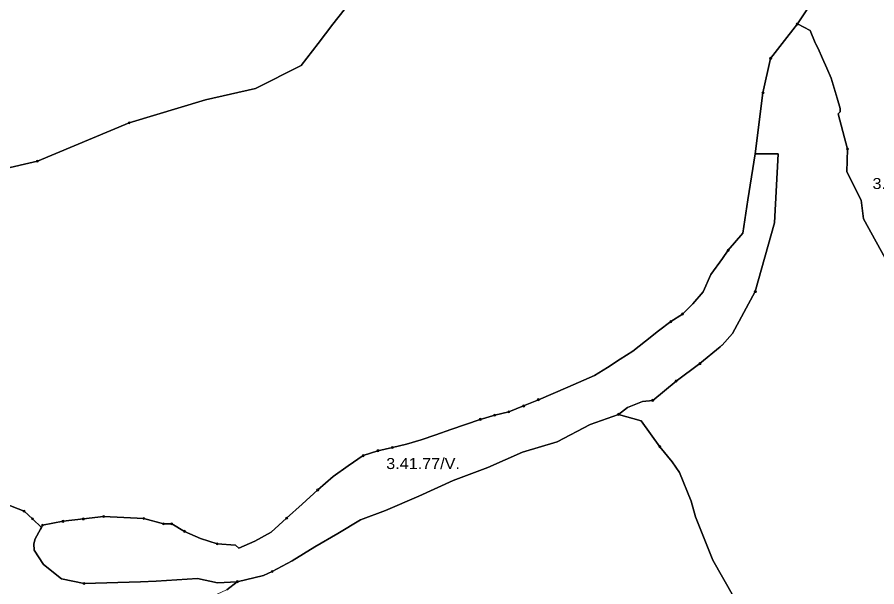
# Model space of a CAD drawing. Extents: x -650455 to -642254, y -1075222 to -1066610.
# Drawn here: x -646705 to -645923, y -1070494 to -1069976 of the extents above; entities that cross this region are included whole.
import ezdxf
from ezdxf.enums import TextEntityAlignment as Align

# ---------------------------------------------------------------- set-up
doc = ezdxf.new("R2010")
doc.units = 0
doc.header["$LTSCALE"] = 4
doc.header["$PDMODE"] = 32
doc.header["$PDSIZE"] = 2
for name, color, linetype, lineweight in [('1', 7, 'Continuous', 25), ('11', 7, 'Continuous', 13), ('12', 7, 'Continuous', 13), ('13', 7, 'Continuous', 13), ('14', 7, 'Continuous', 13), ('15', 7, 'Continuous', 13)]:
    doc.layers.add(name, color=color, linetype=linetype, lineweight=lineweight)
doc.layers.add('2', color=7, linetype='Continuous')

msp = doc.modelspace()

# ---------------------------------------------------------------- linework, layer by layer
at = {"layer": '1'}
for points in [[(-646313.5, -1069705.501), (-646346.5, -1069815.501), (-646359, -1069878.5), (-646385.5, -1069941.501), (-646417.5, -1069982.501), (-646430.839, -1070000), (-646446.211, -1070020.168), (-646487.943, -1070041.034), (-646533.153, -1070051.467), (-646602.706, -1070072.333), (-646686.17, -1070107.109), (-646776.589, -1070127.975)], [(-645892.146, -1070237.292), (-645934.808, -1070159.546), (-645937.054, -1070142.706), (-645949.965, -1070116.884), (-645949.403, -1070096.114), (-645957.823, -1070064.117), (-645955.946, -1070062.197), (-645955.946, -1070059.127), (-645958.753, -1070049.961), (-645961.472, -1070040.795), (-645964.191, -1070031.63), (-645968.226, -1070022.552), (-645972.085, -1070013.649), (-645976.12, -1070004.746), (-645978.592, -1070000), (-645978.839, -1069999.528), (-645983.4, -1069988.169), (-645994.986, -1069982.348), (-645974.12, -1069951.049), (-645958.773, -1069928.03), (-645960, -1069928)], [(-646776.589, -1070127.975), (-646686.17, -1070107.109), (-646602.706, -1070072.333), (-646533.153, -1070051.467), (-646487.943, -1070041.034), (-646446.211, -1070020.168), (-646430.839, -1070000), (-646417.5, -1069982.501), (-646385.5, -1069941.501)], [(-645974.12, -1069951.049), (-645994.986, -1069982.348), (-646008.715, -1070000), (-646019.329, -1070013.647), (-646026.284, -1070044.946), (-646033.24, -1070100.589), (-646040.195, -1070142.321), (-646044.529, -1070172.658), (-646057.984, -1070188.238), (-646063.155, -1070195.784), (-646073.776, -1070210.249), (-646080.764, -1070226.111), (-646090.127, -1070236.942), (-646099.491, -1070246.235), (-646110.112, -1070253.153), (-646121.432, -1070261.469), (-646133.032, -1070270.762), (-646144.631, -1070280.056), (-646156.231, -1070287.393), (-646167.83, -1070294.73), (-646179.43, -1070302.067), (-646203.747, -1070312.828), (-646217.164, -1070318.488), (-646230.58, -1070324.148), (-646243.996, -1070329.808), (-646257.413, -1070335.189), (-646270.27, -1070338.193), (-646283.407, -1070342.037), (-646296.823, -1070346.718), (-646310.24, -1070351.4)], [(-646071.795, -1070469.988), (-646087.776, -1070430.716), (-646091.516, -1070416.436), (-646102.056, -1070390.425), (-646108.856, -1070380.565), (-646120.077, -1070366.964), (-646137.077, -1070343.504), (-646157.707, -1070337.514), (-646149.487, -1070331.235), (-646135.809, -1070325.671), (-646126.536, -1070324.744), (-646105.207, -1070307.24), (-646083.647, -1070291.36), (-646065.1, -1070275.943), (-646064.049, -1070274.932), (-646063.394, -1070274.488), (-646054.106, -1070264.038), (-646033.24, -1070225.784), (-646015.851, -1070163.186), (-646012.374, -1070100.589), (-646033.24, -1070100.589), (-646026.284, -1070044.946), (-646019.329, -1070013.647), (-646008.715, -1070000), (-645994.986, -1069982.348), (-645983.4, -1069988.169), (-645978.839, -1069999.528), (-645978.592, -1070000), (-645976.12, -1070004.746), (-645972.085, -1070013.649), (-645968.226, -1070022.552), (-645964.191, -1070031.63), (-645961.472, -1070040.795), (-645958.753, -1070049.961), (-645955.946, -1070059.127), (-645955.946, -1070062.197), (-645957.823, -1070064.117), (-645949.403, -1070096.114), (-645949.965, -1070116.884), (-645937.054, -1070142.706)], [(-646503.1, -1070459.15), (-646488.566, -1070452.792), (-646473.612, -1070444.756), (-646459.497, -1070431.968), (-646445.382, -1070419.181), (-646431.267, -1070406.254), (-646417.291, -1070394.165), (-646403.456, -1070384.172), (-646389.899, -1070375.019), (-646376.483, -1070370.616), (-646363.346, -1070367.612), (-646350.349, -1070364.607), (-646337.072, -1070360.764), (-646323.656, -1070356.082), (-646310.24, -1070351.4), (-646296.823, -1070346.718), (-646283.407, -1070342.037), (-646270.27, -1070338.193), (-646257.413, -1070335.189), (-646243.996, -1070329.808), (-646230.58, -1070324.148), (-646217.164, -1070318.488), (-646203.747, -1070312.828), (-646179.43, -1070302.067), (-646167.83, -1070294.73), (-646156.231, -1070287.393), (-646144.631, -1070280.056), (-646133.032, -1070270.762), (-646121.432, -1070261.469), (-646110.112, -1070253.153), (-646099.491, -1070246.235), (-646090.127, -1070236.942), (-646080.764, -1070226.111), (-646073.776, -1070210.249), (-646063.155, -1070195.784), (-646057.984, -1070188.238), (-646044.529, -1070172.658), (-646040.195, -1070142.321), (-646033.24, -1070100.589), (-646012.374, -1070100.589)], [(-646012.374, -1070100.589), (-646015.851, -1070163.186), (-646033.24, -1070225.784), (-646054.106, -1070264.038), (-646063.394, -1070274.488), (-646064.049, -1070274.932), (-646065.1, -1070275.943), (-646083.647, -1070291.36), (-646105.207, -1070307.24), (-646126.536, -1070324.744), (-646135.809, -1070325.671), (-646149.487, -1070331.235), (-646157.707, -1070337.514)], [(-645937.054, -1070142.706), (-645934.808, -1070159.546), (-645892.146, -1070237.292), (-645883.165, -1070254.133), (-645864.64, -1070297.356), (-645851.729, -1070325.985), (-645836.012, -1070342.825), (-645812.997, -1070356.859), (-645785.491, -1070380.435), (-645768.65, -1070402.889), (-645763.626, -1070420.193)], [(-646157.707, -1070337.514), (-646183.567, -1070346.768), (-646213.473, -1070362.417), (-646245.003, -1070372.038), (-646276.532, -1070385.832), (-646308.062, -1070397.772), (-646339.359, -1070411.797), (-646369.729, -1070424.896), (-646392.217, -1070433.59), (-646413.082, -1070445.761), (-646433.947, -1070457.932), (-646454.58, -1070470.799), (-646472.663, -1070480.42), (-646480.546, -1070484.129), (-646504.412, -1070489.744), (-646522.293, -1070490.738), (-646540.7, -1070486.685), (-646578.106, -1070489.302), (-646592.291, -1070489.809), (-646643.714, -1070491.413), (-646664.401, -1070487.107), (-646680.613, -1070473.935), (-646689.056, -1070460.931), (-646689.394, -1070455.19), (-646688.291, -1070450.623), (-646683.243, -1070441.891), (-646682.529, -1070440.373), (-646681.566, -1070438.327), (-646662.839, -1070434.764), (-646644.391, -1070432.597), (-646625.944, -1070430.431), (-646607.636, -1070431.34), (-646589.328, -1070432.248), (-646571.44, -1070437.069), (-646564.033, -1070437.069), (-646552.433, -1070443.987), (-646537.759, -1070450.346), (-646522.666, -1070455.307), (-646505.895, -1070456.635), (-646503.1, -1070459.15)], [(-646513.93, -1070496.996), (-646504.412, -1070489.744), (-646480.546, -1070484.129), (-646472.663, -1070480.42), (-646454.58, -1070470.799), (-646433.947, -1070457.932), (-646413.082, -1070445.761), (-646392.217, -1070433.59), (-646369.729, -1070424.896), (-646339.359, -1070411.797), (-646308.062, -1070397.772), (-646276.532, -1070385.832), (-646245.003, -1070372.038), (-646213.473, -1070362.417), (-646183.567, -1070346.768), (-646157.707, -1070337.514), (-646137.077, -1070343.504), (-646120.077, -1070366.964), (-646108.856, -1070380.565), (-646102.056, -1070390.425), (-646091.516, -1070416.436), (-646087.776, -1070430.716), (-646071.795, -1070469.988), (-646053.095, -1070503.139)], [(-646310.24, -1070351.4), (-646323.656, -1070356.082), (-646337.072, -1070360.764), (-646350.349, -1070364.607), (-646363.346, -1070367.612), (-646376.483, -1070370.616), (-646389.899, -1070375.019), (-646403.456, -1070384.172), (-646417.291, -1070394.165), (-646431.267, -1070406.254), (-646445.382, -1070419.181), (-646459.497, -1070431.968), (-646473.612, -1070444.756), (-646488.566, -1070452.792), (-646503.1, -1070459.15), (-646505.895, -1070456.635), (-646522.666, -1070455.307), (-646537.759, -1070450.346), (-646552.433, -1070443.987), (-646564.033, -1070437.069), (-646571.44, -1070437.069), (-646589.328, -1070432.248), (-646607.636, -1070431.34), (-646625.944, -1070430.431), (-646644.391, -1070432.597), (-646662.839, -1070434.764), (-646681.566, -1070438.327), (-646682.529, -1070440.373), (-646690.65, -1070432.527), (-646698.336, -1070425.54), (-646716.085, -1070418.622)], [(-646895.25, -1070424.491), (-646877.361, -1070423.583), (-646859.613, -1070422.675), (-646841.444, -1070420.229), (-646823.276, -1070420.998), (-646805.248, -1070421.766), (-646787.22, -1070420.299), (-646769.192, -1070417.294), (-646751.583, -1070414.289), (-646733.694, -1070416.456), (-646716.085, -1070418.622), (-646698.336, -1070425.54), (-646690.65, -1070432.527), (-646682.529, -1070440.373)], [(-646682.529, -1070440.373), (-646683.243, -1070441.891), (-646688.291, -1070450.623), (-646689.394, -1070455.19), (-646689.056, -1070460.931), (-646680.613, -1070473.935), (-646664.401, -1070487.107), (-646643.714, -1070491.413), (-646592.291, -1070489.809), (-646578.106, -1070489.302), (-646540.7, -1070486.685), (-646522.293, -1070490.738), (-646504.412, -1070489.744), (-646513.93, -1070496.996)], [(-645920.242, -1070713.679), (-645927.962, -1070711.588), (-645950.317, -1070694.38), (-645965.032, -1070672.106), (-645972.912, -1070658.757), (-645982.884, -1070639.297), (-645992.731, -1070624.604), (-645999.333, -1070608.761), (-646000.735, -1070603.916), (-646002.692, -1070598.86), (-646005.067, -1070591.608), (-646007.731, -1070584.143), (-646009.999, -1070577.784), (-646016.721, -1070567.029), (-646017.857, -1070565.514), (-646032.694, -1070537.65), (-646053.095, -1070503.139), (-646071.795, -1070469.988)]]:
    msp.add_lwpolyline(points, dxfattribs=at)
at = {"layer": '11'}
for p, q in [((-646243.996, -1070329.808), (-646230.58, -1070324.148)), ((-646270.27, -1070338.193), (-646257.413, -1070335.189)), ((-646257.413, -1070335.189), (-646243.996, -1070329.808)), ((-646698.336, -1070425.54), (-646690.65, -1070432.527)), ((-646662.839, -1070434.764), (-646644.391, -1070432.597)), ((-646644.391, -1070432.597), (-646625.944, -1070430.431)), ((-646589.328, -1070432.248), (-646571.44, -1070437.069)), ((-646571.44, -1070437.069), (-646564.033, -1070437.069)), ((-646564.033, -1070437.069), (-646552.433, -1070443.987))]:
    msp.add_line(p, q, dxfattribs=at)
for points in [[(-645994.986, -1069982.348), (-645974.12, -1069951.049), (-645958.773, -1069928.03), (-645960, -1069928), (-645957.5, -1069916.501), (-645945.5, -1069826), (-645941.5, -1069786)], [(-646359, -1069878.5), (-646385.5, -1069941.501), (-646417.5, -1069982.501), (-646430.839, -1070000), (-646446.211, -1070020.168), (-646487.943, -1070041.034), (-646533.153, -1070051.467), (-646602.706, -1070072.333), (-646686.17, -1070107.109)], [(-646019.329, -1070013.647), (-646008.715, -1070000), (-645994.986, -1069982.348)], [(-646057.984, -1070188.238), (-646044.529, -1070172.658), (-646040.195, -1070142.321), (-646033.24, -1070100.589), (-646026.284, -1070044.946), (-646019.329, -1070013.647)], [(-646686.17, -1070107.109), (-646776.589, -1070127.975), (-646839.187, -1070117.542)], [(-646099.491, -1070246.235), (-646090.127, -1070236.942), (-646080.764, -1070226.111), (-646073.776, -1070210.249), (-646063.155, -1070195.784), (-646057.984, -1070188.238)], [(-646230.58, -1070324.148), (-646217.164, -1070318.488), (-646203.747, -1070312.828), (-646179.43, -1070302.067), (-646167.83, -1070294.73), (-646156.231, -1070287.393), (-646144.631, -1070280.056), (-646133.032, -1070270.762), (-646121.432, -1070261.469), (-646110.112, -1070253.153), (-646099.491, -1070246.235)], [(-646363.346, -1070367.612), (-646350.349, -1070364.607), (-646337.072, -1070360.764), (-646323.656, -1070356.082), (-646310.24, -1070351.4), (-646296.823, -1070346.718), (-646283.407, -1070342.037), (-646270.27, -1070338.193)], [(-646552.433, -1070443.987), (-646537.759, -1070450.346), (-646522.666, -1070455.307), (-646505.895, -1070456.635), (-646503.1, -1070459.15), (-646488.566, -1070452.792), (-646473.612, -1070444.756), (-646459.497, -1070431.968), (-646445.382, -1070419.181), (-646431.267, -1070406.254), (-646417.291, -1070394.165), (-646403.456, -1070384.172), (-646389.899, -1070375.019), (-646376.483, -1070370.616), (-646363.346, -1070367.612)], [(-646948.775, -1070423.304), (-646930.747, -1070423.513), (-646912.999, -1070424.002), (-646895.25, -1070424.491), (-646877.361, -1070423.583), (-646859.613, -1070422.675), (-646841.444, -1070420.229), (-646823.276, -1070420.998), (-646805.248, -1070421.766), (-646787.22, -1070420.299), (-646769.192, -1070417.294), (-646751.583, -1070414.289), (-646733.694, -1070416.456), (-646716.085, -1070418.622), (-646698.336, -1070425.54)], [(-646690.65, -1070432.527), (-646682.529, -1070440.373), (-646681.566, -1070438.327), (-646662.839, -1070434.764)], [(-646625.944, -1070430.431), (-646607.636, -1070431.34), (-646589.328, -1070432.248)]]:
    msp.add_lwpolyline(points, dxfattribs=at)
for p in [(-645994.986, -1069982.348), (-646019.329, -1070013.647), (-646686.17, -1070107.109), (-646057.984, -1070188.238), (-646099.491, -1070246.235), (-646230.58, -1070324.148), (-646257.413, -1070335.189), (-646243.996, -1070329.808), (-646270.27, -1070338.193), (-646363.346, -1070367.612), (-646698.336, -1070425.54), (-646690.65, -1070432.527), (-646662.839, -1070434.764), (-646644.391, -1070432.597), (-646625.944, -1070430.431), (-646589.328, -1070432.248), (-646571.44, -1070437.069), (-646564.033, -1070437.069), (-646552.433, -1070443.987)]:
    msp.add_point(p, dxfattribs=at)
at = {"layer": '12'}
for points in [[(-645994.986, -1069982.348), (-646008.715, -1070000), (-646019.329, -1070013.647), (-646026.284, -1070044.946)], [(-645892.146, -1070237.292), (-645934.808, -1070159.546), (-645937.054, -1070142.706), (-645949.965, -1070116.884), (-645949.403, -1070096.114), (-645957.823, -1070064.117), (-645955.946, -1070062.197), (-645955.946, -1070059.127), (-645958.753, -1070049.961), (-645961.472, -1070040.795), (-645964.191, -1070031.63), (-645968.226, -1070022.552), (-645972.085, -1070013.649), (-645976.12, -1070004.746), (-645978.592, -1070000), (-645978.839, -1069999.528), (-645983.4, -1069988.169), (-645994.986, -1069982.348)], [(-646026.284, -1070044.946), (-646033.24, -1070100.589), (-646012.374, -1070100.589), (-646015.851, -1070163.186), (-646033.24, -1070225.784)], [(-646033.24, -1070225.784), (-646054.106, -1070264.038), (-646063.394, -1070274.488), (-646064.049, -1070274.932), (-646065.1, -1070275.943), (-646083.647, -1070291.36)], [(-646083.647, -1070291.36), (-646105.207, -1070307.24), (-646126.536, -1070324.744), (-646135.809, -1070325.671), (-646149.487, -1070331.235), (-646157.707, -1070337.514), (-646137.077, -1070343.504), (-646120.077, -1070366.964), (-646108.856, -1070380.565), (-646102.056, -1070390.425), (-646091.516, -1070416.436), (-646087.776, -1070430.716), (-646071.795, -1070469.988), (-646053.095, -1070503.139), (-646032.694, -1070537.65), (-646017.857, -1070565.514), (-646016.721, -1070567.029), (-646009.999, -1070577.784), (-646007.731, -1070584.143), (-646005.067, -1070591.608), (-646002.692, -1070598.86), (-646000.735, -1070603.916)], [(-646157.707, -1070337.514), (-646183.567, -1070346.768), (-646213.473, -1070362.417), (-646245.003, -1070372.038), (-646276.532, -1070385.832), (-646308.062, -1070397.772), (-646339.359, -1070411.797), (-646369.729, -1070424.896), (-646392.217, -1070433.59), (-646413.082, -1070445.761), (-646433.947, -1070457.932), (-646454.58, -1070470.799), (-646472.663, -1070480.42), (-646480.546, -1070484.129), (-646504.412, -1070489.744)], [(-646120.077, -1070366.964), (-646137.077, -1070343.504), (-646157.707, -1070337.514)], [(-646014.913, -1070609.041), (-646008.134, -1070603.149), (-646004.664, -1070600.284), (-646002.692, -1070598.86), (-646005.067, -1070591.608), (-646007.731, -1070584.143), (-646009.999, -1070577.784), (-646016.721, -1070567.029), (-646017.857, -1070565.514), (-646032.694, -1070537.65), (-646053.095, -1070503.139), (-646071.795, -1070469.988), (-646087.776, -1070430.716), (-646091.516, -1070416.436), (-646102.056, -1070390.425), (-646108.856, -1070380.565), (-646120.077, -1070366.964)], [(-646504.412, -1070489.744), (-646513.93, -1070496.996), (-646514.69, -1070497.343), (-646529.926, -1070504.299)]]:
    msp.add_lwpolyline(points, dxfattribs=at)
for p in [(-645994.986, -1069982.348), (-646026.284, -1070044.946), (-646033.24, -1070225.784), (-646083.647, -1070291.36), (-646157.707, -1070337.514), (-646120.077, -1070366.964), (-646504.412, -1070489.744)]:
    msp.add_point(p, dxfattribs=at)
at = {"layer": '13'}
for points in [[(-646602.706, -1070072.333), (-646533.153, -1070051.467), (-646487.943, -1070041.034), (-646446.211, -1070020.168), (-646430.839, -1070000), (-646417.5, -1069982.501), (-646385.5, -1069941.501)], [(-646776.589, -1070127.975), (-646686.17, -1070107.109), (-646602.706, -1070072.333)]]:
    msp.add_lwpolyline(points, dxfattribs=at)
msp.add_point((-646602.706, -1070072.333), dxfattribs=at)
at = {"layer": '14'}
msp.add_lwpolyline([(-646514.69, -1070497.343), (-646513.93, -1070496.996), (-646504.412, -1070489.744), (-646522.293, -1070490.738), (-646540.7, -1070486.685), (-646578.106, -1070489.302), (-646592.291, -1070489.809), (-646643.714, -1070491.413), (-646664.401, -1070487.107), (-646680.613, -1070473.935), (-646689.056, -1070460.931), (-646689.394, -1070455.19), (-646688.291, -1070450.623), (-646683.243, -1070441.891), (-646682.529, -1070440.373), (-646690.65, -1070432.527), (-646698.336, -1070425.54), (-646716.085, -1070418.622), (-646733.694, -1070416.456), (-646751.583, -1070414.289), (-646769.192, -1070417.294)], dxfattribs=at)
at = {"layer": '15'}
for p, q in [((-646126.536, -1070324.744), (-646105.207, -1070307.24)), ((-646376.483, -1070370.616), (-646389.899, -1070375.019)), ((-646662.839, -1070434.764), (-646681.566, -1070438.327))]:
    msp.add_line(p, q, dxfattribs=at)
for points in [[(-645945.5, -1069826), (-645957.5, -1069916.501), (-645960, -1069928), (-645958.773, -1069928.03), (-645974.12, -1069951.049), (-645994.986, -1069982.348)], [(-645994.986, -1069982.348), (-645983.4, -1069988.169), (-645978.839, -1069999.528), (-645978.592, -1070000), (-645976.12, -1070004.746), (-645972.085, -1070013.649), (-645968.226, -1070022.552), (-645964.191, -1070031.63), (-645961.472, -1070040.795), (-645958.753, -1070049.961), (-645955.946, -1070059.127), (-645955.946, -1070062.197), (-645957.823, -1070064.117), (-645949.403, -1070096.114)], [(-646105.207, -1070307.24), (-646083.647, -1070291.36), (-646065.1, -1070275.943), (-646064.049, -1070274.932), (-646063.394, -1070274.488), (-646054.106, -1070264.038), (-646033.24, -1070225.784), (-646015.851, -1070163.186), (-646012.374, -1070100.589), (-646033.24, -1070100.589), (-646040.195, -1070142.321), (-646044.529, -1070172.658), (-646057.984, -1070188.238), (-646063.155, -1070195.784), (-646073.776, -1070210.249), (-646080.764, -1070226.111), (-646090.127, -1070236.942), (-646099.491, -1070246.235), (-646110.112, -1070253.153)], [(-645949.403, -1070096.114), (-645949.965, -1070116.884), (-645937.054, -1070142.706), (-645934.808, -1070159.546), (-645892.146, -1070237.292), (-645883.165, -1070254.133), (-645864.64, -1070297.356), (-645851.729, -1070325.985), (-645836.012, -1070342.825), (-645812.997, -1070356.859), (-645785.491, -1070380.435), (-645768.65, -1070402.889), (-645763.626, -1070420.193), (-645741.986, -1070441.834), (-645729.814, -1070460.091), (-645712.054, -1070466.012), (-645711, -1070465.5), (-645695.5, -1070468.001), (-645688.022, -1070470.362)], [(-646110.112, -1070253.153), (-646121.432, -1070261.469), (-646133.032, -1070270.762), (-646144.631, -1070280.056), (-646156.231, -1070287.393), (-646167.83, -1070294.73), (-646179.43, -1070302.067), (-646203.747, -1070312.828), (-646217.164, -1070318.488), (-646230.58, -1070324.148), (-646243.996, -1070329.808), (-646257.413, -1070335.189), (-646270.27, -1070338.193), (-646283.407, -1070342.037)], [(-646213.473, -1070362.417), (-646183.567, -1070346.768), (-646157.707, -1070337.514), (-646149.487, -1070331.235), (-646135.809, -1070325.671), (-646126.536, -1070324.744)], [(-646283.407, -1070342.037), (-646296.823, -1070346.718), (-646310.24, -1070351.4), (-646323.656, -1070356.082), (-646337.072, -1070360.764), (-646350.349, -1070364.607), (-646363.346, -1070367.612), (-646376.483, -1070370.616)], [(-646472.663, -1070480.42), (-646454.58, -1070470.799), (-646433.947, -1070457.932), (-646413.082, -1070445.761), (-646392.217, -1070433.59), (-646369.729, -1070424.896), (-646339.359, -1070411.797), (-646308.062, -1070397.772), (-646276.532, -1070385.832), (-646245.003, -1070372.038), (-646213.473, -1070362.417)], [(-646389.899, -1070375.019), (-646403.456, -1070384.172), (-646417.291, -1070394.165), (-646431.267, -1070406.254)], [(-646431.267, -1070406.254), (-646445.382, -1070419.181), (-646459.497, -1070431.968)], [(-646625.944, -1070430.431), (-646644.391, -1070432.597), (-646662.839, -1070434.764)], [(-646571.44, -1070437.069), (-646589.328, -1070432.248), (-646607.636, -1070431.34), (-646625.944, -1070430.431)], [(-646459.497, -1070431.968), (-646473.612, -1070444.756), (-646488.566, -1070452.792), (-646503.1, -1070459.15), (-646505.895, -1070456.635), (-646522.666, -1070455.307)], [(-646681.566, -1070438.327), (-646682.529, -1070440.373), (-646683.243, -1070441.891), (-646688.291, -1070450.623), (-646689.394, -1070455.19), (-646689.056, -1070460.931), (-646680.613, -1070473.935), (-646664.401, -1070487.107), (-646643.714, -1070491.413)], [(-646522.666, -1070455.307), (-646537.759, -1070450.346), (-646552.433, -1070443.987), (-646564.033, -1070437.069), (-646571.44, -1070437.069)], [(-646643.714, -1070491.413), (-646592.291, -1070489.809), (-646578.106, -1070489.302), (-646540.7, -1070486.685), (-646522.293, -1070490.738), (-646504.412, -1070489.744), (-646480.546, -1070484.129), (-646472.663, -1070480.42)]]:
    msp.add_lwpolyline(points, dxfattribs=at)
for p in [(-645994.986, -1069982.348), (-645949.403, -1070096.114), (-646110.112, -1070253.153), (-646105.207, -1070307.24), (-646126.536, -1070324.744), (-646283.407, -1070342.037), (-646389.899, -1070375.019), (-646376.483, -1070370.616), (-646431.267, -1070406.254), (-646662.839, -1070434.764), (-646625.944, -1070430.431), (-646571.44, -1070437.069), (-646459.497, -1070431.968), (-646681.566, -1070438.327), (-646522.666, -1070455.307), (-646472.663, -1070480.42), (-646643.714, -1070491.413)]:
    msp.add_point(p, dxfattribs=at)

# ---------------------------------------------------------------- texts
at = {"layer": '2', "width": 1.1}
for p in [(-645893.136, -1070132.488), (-646335.406, -1070387.24)]:
    msp.add_text('3.41.77/V.', height=10, dxfattribs=at).set_placement(p, align=Align.CENTER)

doc.saveas('drawing.dxf')
